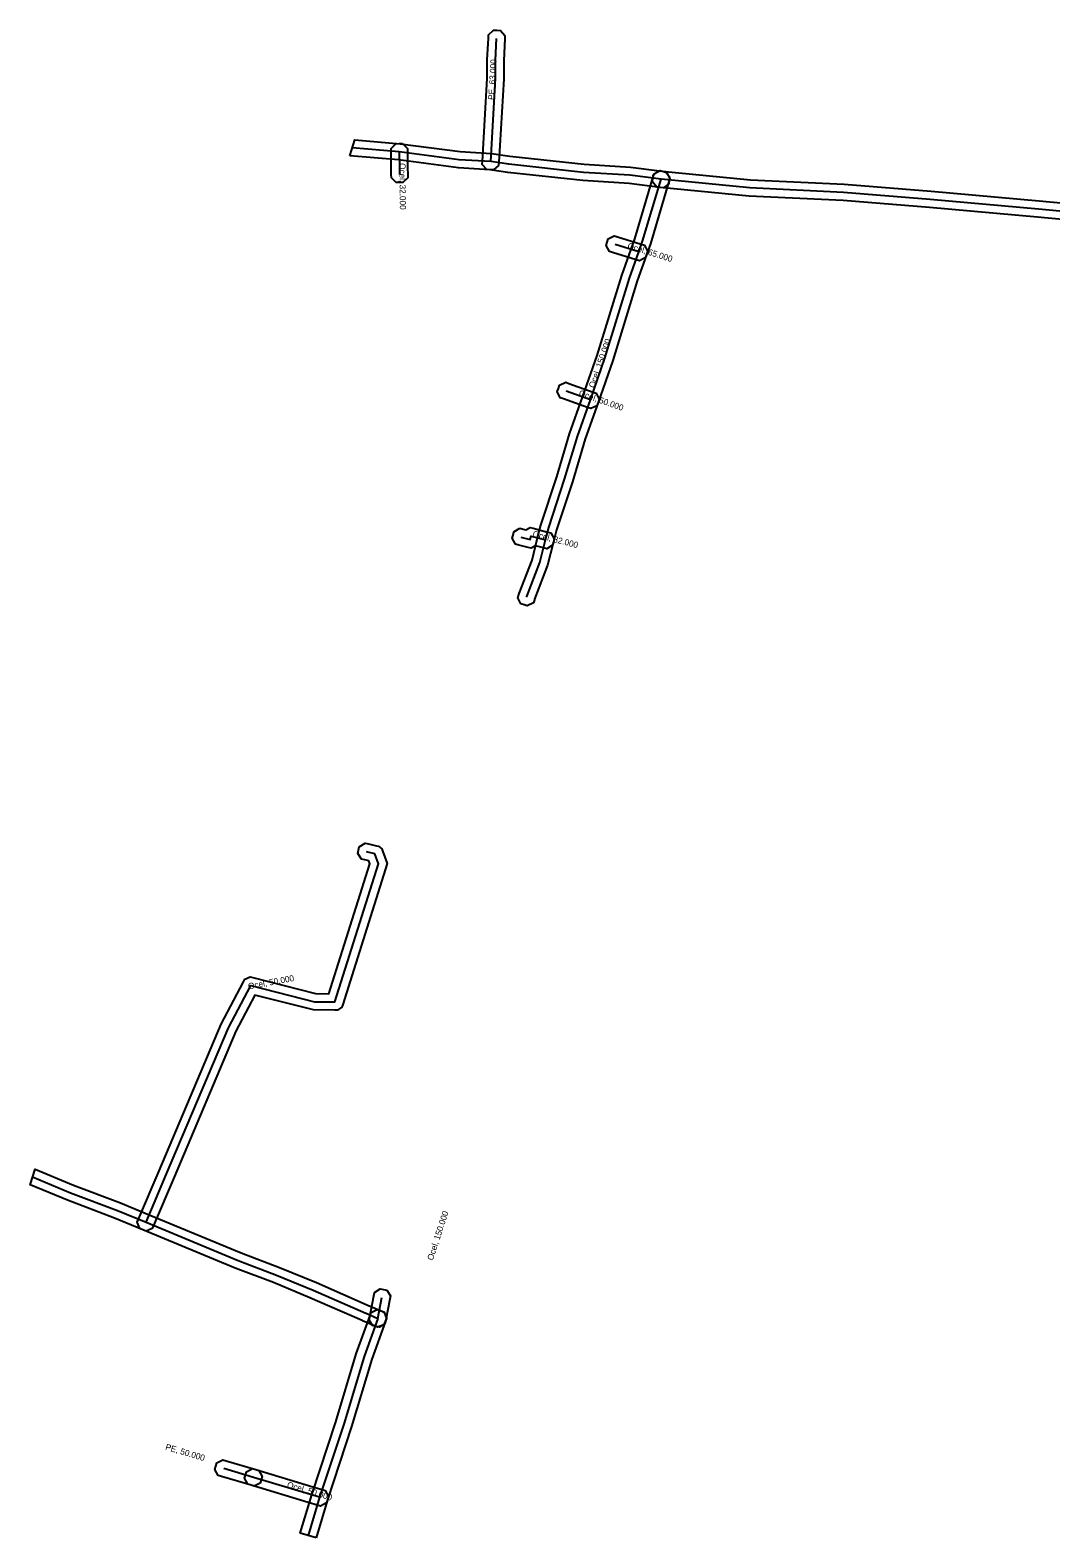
# Model space of a CAD drawing. Extents: x -888412 to -888163, y -1022526 to -1022295.
# Drawn here: x -888412.2 to -888287.5, y -1022487.2 to -1022303.1 of the extents above; entities that cross this region are included whole.
import ezdxf

# ---------------------------------------------------------------- set-up
doc = ezdxf.new("R2010")
doc.units = 0
for name, color, linetype in [('Vrstva 1', 7, 'Continuous'), ('Vrstva 14', 7, 'Continuous'), ('Vrstva 20', 7, 'Continuous')]:
    doc.layers.add(name, color=color, linetype=linetype)

msp = doc.modelspace()

# ---------------------------------------------------------------- linework, layer by layer
at = {"layer": 'Vrstva 1'}
for points in [[(-888356.401, -1022320.084), (-888356.952, -1022319.465), (-888356.928, -1022319.052), (-888356.34, -1022308.951), (-888356.34, -1022306.705), (-888356.209, -1022304.031), (-888356.189, -1022303.617), (-888355.575, -1022303.061), (-888355.161, -1022303.081), (-888354.747, -1022303.101), (-888354.191, -1022303.715), (-888354.211, -1022304.129), (-888354.34, -1022306.755), (-888354.34, -1022309.009), (-888354.932, -1022319.168), (-888354.956, -1022319.581), (-888355.575, -1022320.132), (-888355.988, -1022320.108)], [(-888373.124, -1022318.413), (-888372.517, -1022316.457), (-888366.983, -1022316.925), (-888359.665, -1022317.884), (-888355.826, -1022318.114), (-888353.582, -1022318.448), (-888344.516, -1022319.443), (-888338.845, -1022319.773), (-888335, -1022320.279), (-888334.589, -1022320.333), (-888334.085, -1022320.99), (-888334.139, -1022321.4), (-888334.193, -1022321.811), (-888334.85, -1022322.315), (-888335.26, -1022322.261), (-888339.033, -1022321.765), (-888344.684, -1022321.437), (-888353.838, -1022320.432), (-888356.034, -1022320.106), (-888359.855, -1022319.876), (-888367.197, -1022318.915)], [(-888366.686, -1022316.916), (-888366.094, -1022317.496), (-888366.09, -1022317.91), (-888366.07, -1022319.87), (-888366.062, -1022320.666), (-888366.058, -1022321.08), (-888366.638, -1022321.672), (-888367.052, -1022321.676), (-888367.466, -1022321.68), (-888368.058, -1022321.1), (-888368.062, -1022320.686), (-888368.07, -1022319.89), (-888368.09, -1022317.93), (-888368.094, -1022317.516), (-888367.514, -1022316.924), (-888367.1, -1022316.92)], [(-888352.247, -1022373.11), (-888352.62, -1022372.371), (-888352.49, -1022371.977), (-888352.452, -1022371.863), (-888350.885, -1022367.778), (-888350.203, -1022365.066), (-888349.811, -1022363.51), (-888347.854, -1022357.601), (-888346.301, -1022352.36), (-888344.703, -1022347.858), (-888342.93, -1022342.788), (-888339.93, -1022333.026), (-888338.794, -1022329.811), (-888338.341, -1022328.53), (-888336.088, -1022320.984), (-888335.97, -1022320.587), (-888335.241, -1022320.194), (-888334.844, -1022320.312), (-888334.447, -1022320.43), (-888334.054, -1022321.159), (-888334.172, -1022321.556), (-888336.439, -1022329.15), (-888336.908, -1022330.477), (-888338.03, -1022333.654), (-888341.03, -1022343.412), (-888342.817, -1022348.522), (-888344.399, -1022352.98), (-888345.946, -1022358.199), (-888347.889, -1022364.07), (-888348.263, -1022365.554), (-888348.975, -1022368.382), (-888350.568, -1022372.535), (-888350.59, -1022372.603), (-888350.72, -1022372.997), (-888351.459, -1022373.37), (-888351.853, -1022373.24)], [(-888337.02, -1022330.838), (-888337.754, -1022331.222), (-888338.15, -1022331.098), (-888341.039, -1022330.194), (-888341.434, -1022330.071), (-888341.818, -1022329.337), (-888341.694, -1022328.941), (-888341.571, -1022328.546), (-888340.837, -1022328.162), (-888340.441, -1022328.286), (-888337.552, -1022329.19), (-888337.157, -1022329.313), (-888336.773, -1022330.047), (-888336.897, -1022330.443)], [(-888342.956, -1022348.915), (-888343.704, -1022349.271), (-888344.094, -1022349.132), (-888347.054, -1022348.082), (-888347.445, -1022347.944), (-888347.801, -1022347.196), (-888347.662, -1022346.806), (-888347.524, -1022346.415), (-888346.776, -1022346.059), (-888346.386, -1022346.198), (-888343.426, -1022347.248), (-888343.035, -1022347.386), (-888342.679, -1022348.134), (-888342.818, -1022348.524)], [(-888352.378, -1022363.888), (-888351.977, -1022363.992), (-888351.658, -1022364.075), (-888351.121, -1022363.782), (-888350.737, -1022363.883), (-888348.98, -1022364.343), (-888348.579, -1022364.448), (-888348.161, -1022365.162), (-888348.266, -1022365.563), (-888348.371, -1022365.964), (-888349.085, -1022366.382), (-888349.486, -1022366.277), (-888350.451, -1022366.024), (-888350.988, -1022366.318), (-888351.373, -1022366.218), (-888352.483, -1022365.928), (-888352.884, -1022365.823), (-888353.302, -1022365.108), (-888353.198, -1022364.707), (-888353.093, -1022364.306)], [(-888398.77, -1022449.384), (-888399.082, -1022448.616), (-888398.92, -1022448.235), (-888396.421, -1022442.33), (-888388.844, -1022424.431), (-888386.104, -1022419.243), (-888385.943, -1022418.937), (-888385.31, -1022418.656), (-888384.974, -1022418.741), (-888377.299, -1022420.692), (-888375.68, -1022420.711), (-888370.678, -1022404.869), (-888370.824, -1022404.48), (-888371.295, -1022404.377), (-888371.7, -1022404.288), (-888372.146, -1022403.59), (-888372.057, -1022403.185), (-888371.968, -1022402.78), (-888371.27, -1022402.334), (-888370.865, -1022402.423), (-888369.865, -1022402.643), (-888369.618, -1022402.698), (-888369.234, -1022403.03), (-888369.144, -1022403.267), (-888368.562, -1022404.811), (-888373.996, -1022422.021), (-888374.096, -1022422.336), (-888374.632, -1022422.724), (-888374.962, -1022422.72), (-888377.561, -1022422.688), (-888384.703, -1022420.873), (-888387.036, -1022425.289), (-888394.579, -1022443.11), (-888397.078, -1022449.015), (-888397.24, -1022449.396), (-888398.008, -1022449.708), (-888398.389, -1022449.546)], [(-888407.589, -1022445.94), (-888412.151, -1022444.044), (-888411.555, -1022442.126), (-888406.851, -1022444.08), (-888401.111, -1022446.25), (-888397.616, -1022447.701), (-888386.392, -1022452.36), (-888381.702, -1022454.129), (-888377.209, -1022455.99), (-888370.766, -1022458.804), (-888370.727, -1022458.823), (-888369.322, -1022459.433), (-888368.942, -1022459.597), (-888368.638, -1022460.368), (-888368.803, -1022460.748), (-888368.967, -1022461.128), (-888369.738, -1022461.432), (-888370.118, -1022461.267), (-888371.573, -1022460.637), (-888371.614, -1022460.616), (-888377.991, -1022457.83), (-888382.438, -1022455.989), (-888387.128, -1022454.22), (-888398.382, -1022449.549), (-888401.849, -1022448.11)], [(-888370.322, -1022461.249), (-888370.782, -1022460.56), (-888370.701, -1022460.154), (-888370.191, -1022457.604), (-888370.109, -1022457.198), (-888369.42, -1022456.738), (-888369.014, -1022456.819), (-888368.608, -1022456.901), (-888368.148, -1022457.59), (-888368.229, -1022457.996), (-888368.739, -1022460.546), (-888368.821, -1022460.952), (-888369.51, -1022461.412), (-888369.916, -1022461.331)], [(-888377.255, -1022487.152), (-888379.174, -1022486.589), (-888377.764, -1022481.9), (-888374.824, -1022472.97), (-888372.34, -1022464.697), (-888370.661, -1022460.013), (-888370.521, -1022459.623), (-888369.773, -1022459.269), (-888369.383, -1022459.409), (-888368.993, -1022459.549), (-888368.639, -1022460.297), (-888368.779, -1022460.687), (-888370.44, -1022465.323), (-888372.916, -1022473.57), (-888375.856, -1022482.5)], [(-888384.064, -1022480.458), (-888384.793, -1022480.851), (-888385.19, -1022480.732), (-888388.807, -1022479.648), (-888389.204, -1022479.529), (-888389.597, -1022478.8), (-888389.478, -1022478.403), (-888389.359, -1022478.006), (-888388.63, -1022477.613), (-888388.233, -1022477.732), (-888384.616, -1022478.816), (-888384.219, -1022478.935), (-888383.826, -1022479.664), (-888383.945, -1022480.061)], [(-888375.971, -1022482.884), (-888376.701, -1022483.277), (-888377.097, -1022483.158), (-888378.197, -1022482.828), (-888385.19, -1022480.732), (-888385.587, -1022480.613), (-888385.98, -1022479.884), (-888385.861, -1022479.487), (-888385.742, -1022479.09), (-888385.013, -1022478.697), (-888384.616, -1022478.816), (-888377.623, -1022480.912), (-888376.523, -1022481.242), (-888376.126, -1022481.361), (-888375.733, -1022482.091), (-888375.852, -1022482.487)]]:
    msp.add_lwpolyline(points, close=True, dxfattribs=at)
msp.add_lwpolyline([(-888279.574, -1022326.806), (-888289.161, -1022325.896), (-888302.345, -1022324.726), (-888312.905, -1022323.868), (-888324.362, -1022323.318), (-888335.226, -1022322.265), (-888335.639, -1022322.225), (-888336.165, -1022321.586), (-888336.125, -1022321.174), (-888336.085, -1022320.761), (-888335.446, -1022320.235), (-888335.034, -1022320.275), (-888324.218, -1022321.322), (-888312.775, -1022321.872), (-888302.175, -1022322.734), (-888288.979, -1022323.904), (-888279.386, -1022324.814)], dxfattribs=at)
at = {"layer": 'Vrstva 14'}
for p, q in [((-888367.09, -1022317.92), (-888372.821, -1022317.435)), ((-888337.851, -1022330.144), (-888340.74, -1022329.24)), ((-888343.76, -1022348.19), (-888346.72, -1022347.14)), ((-888351.54, -1022372.29), (-888351.51, -1022372.199)), ((-888369.72, -1022460.35), (-888369.21, -1022457.8)), ((-888384.903, -1022479.774), (-888388.52, -1022478.69)), ((-888376.81, -1022482.2), (-888378.214, -1022486.871))]:
    msp.add_line(p, q, dxfattribs=at)
for points in [[(-888355.93, -1022319.11), (-888355.34, -1022308.98), (-888355.34, -1022306.73), (-888355.21, -1022304.08)], [(-888355.93, -1022319.11), (-888359.76, -1022318.88), (-888367.09, -1022317.92)], [(-888367.09, -1022317.92), (-888367.07, -1022319.88), (-888367.062, -1022320.676)], [(-888335.13, -1022321.27), (-888338.939, -1022320.769), (-888344.6, -1022320.44), (-888353.71, -1022319.44), (-888355.93, -1022319.11)], [(-888337.851, -1022330.144), (-888337.39, -1022328.84), (-888335.13, -1022321.27)], [(-888188.48, -1022336.44), (-888197.907, -1022337.01), (-888204.95, -1022336.76), (-888211.27, -1022331.7), (-888221.76, -1022331), (-888228, -1022330.35), (-888238.67, -1022329.42), (-888250.25, -1022328.57), (-888260.39, -1022327.69), (-888265.99, -1022327.09), (-888279.48, -1022325.81), (-888289.07, -1022324.9), (-888302.26, -1022323.73), (-888312.84, -1022322.87), (-888324.29, -1022322.32), (-888335.13, -1022321.27)], [(-888343.76, -1022348.19), (-888341.98, -1022343.1), (-888338.98, -1022333.34), (-888337.851, -1022330.144)], [(-888349.233, -1022365.31), (-888348.85, -1022363.79), (-888346.9, -1022357.9), (-888345.35, -1022352.67), (-888343.76, -1022348.19)], [(-888352.23, -1022364.96), (-888351.12, -1022365.25), (-888350.99, -1022364.85), (-888349.233, -1022365.31)], [(-888351.51, -1022372.199), (-888349.93, -1022368.08), (-888349.233, -1022365.31)], [(-888397.999, -1022448.625), (-888395.5, -1022442.72), (-888387.94, -1022424.86), (-888385.22, -1022419.71), (-888377.43, -1022421.69), (-888374.95, -1022421.72), (-888369.62, -1022404.84), (-888370.08, -1022403.62), (-888371.08, -1022403.4)], [(-888411.853, -1022443.085), (-888407.22, -1022445.01), (-888401.48, -1022447.18), (-888397.999, -1022448.625)], [(-888397.999, -1022448.625), (-888386.76, -1022453.29), (-888382.07, -1022455.059)], [(-888382.07, -1022455.059), (-888377.6, -1022456.91), (-888371.19, -1022459.71)], [(-888371.19, -1022459.71), (-888371.15, -1022459.73), (-888369.72, -1022460.35)], [(-888369.72, -1022460.35), (-888371.39, -1022465.01), (-888373.87, -1022473.27), (-888376.81, -1022482.2)], [(-888376.81, -1022482.2), (-888377.91, -1022481.87), (-888384.903, -1022479.774)]]:
    msp.add_lwpolyline(points, dxfattribs=at)

# ---------------------------------------------------------------- texts
at = {"layer": 'Vrstva 20'}
for s, rotation, p in [('PE, 63.000', 86.66668, (-888355.492, -1022311.598)), ('Ocel, 32.000', 270.58461, (-888367.076, -1022319.298)), ('Ocel, 65.000', 342.62454, (-888339.296, -1022329.692)), ('Ocel, 150.000', 70.72499, (-888343.276, -1022346.806)), ('Ocel, 50.000', 340.4689, (-888345.24, -1022347.665)), ('Ocel, 32.000', 345.32867, (-888350.87, -1022364.881)), ('Ocel, 50.000', 10.52684, (-888385.473, -1022420.189)), ('Ocel, 150.000', 72.01793, (-888362.99, -1022453.33)), ('PE, 50.000', 343.4017, (-888395.71, -1022476.37)), ('Ocel, 50.000', 343.31501, (-888380.856, -1022480.987))]:
    msp.add_text(s, height=0.75, rotation=rotation, dxfattribs=at).set_placement(p)

doc.saveas('drawing.dxf')
